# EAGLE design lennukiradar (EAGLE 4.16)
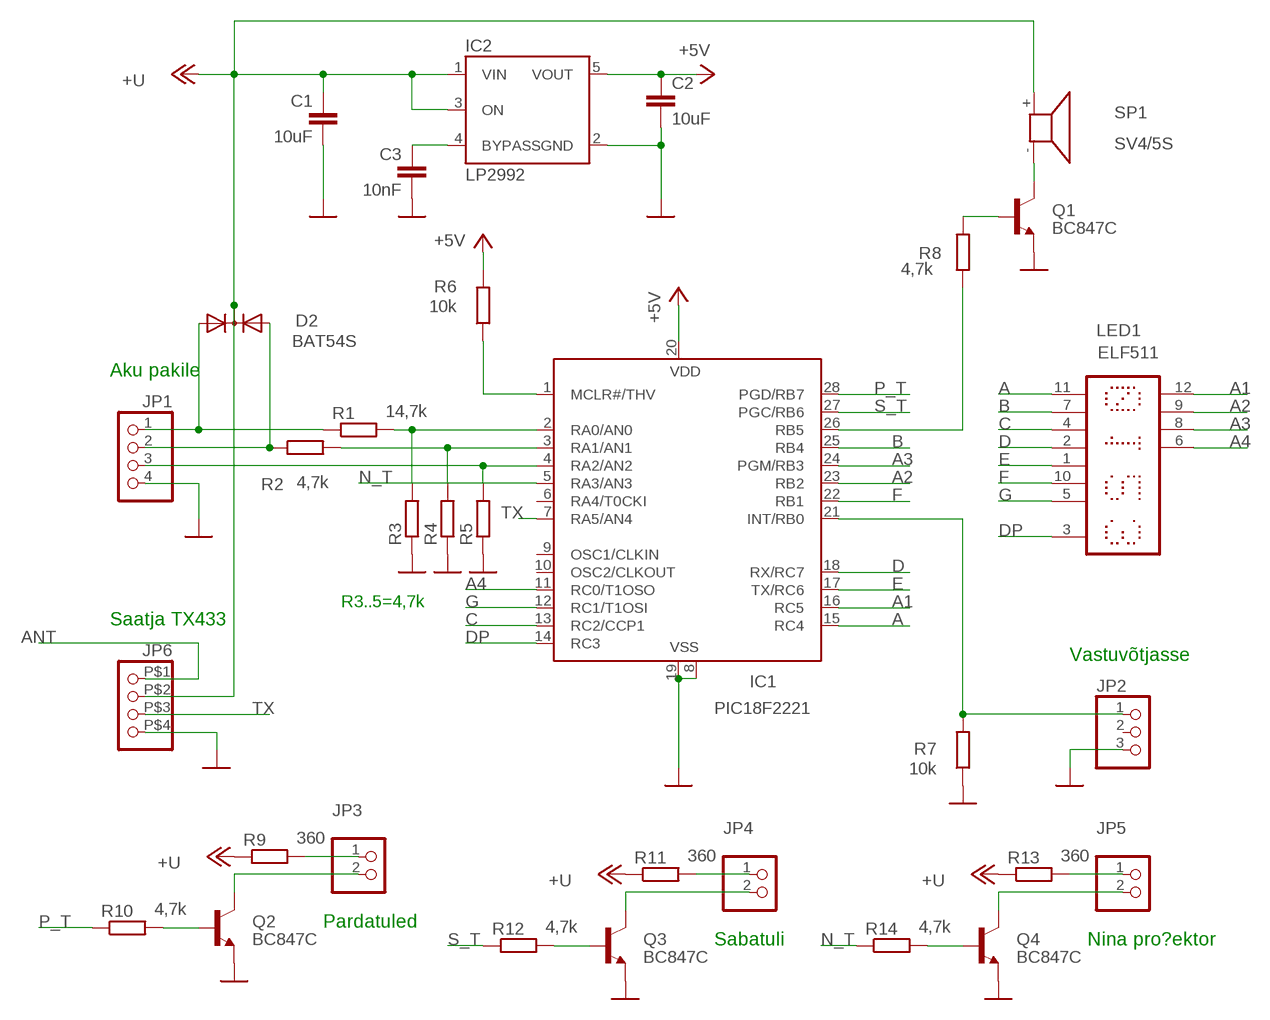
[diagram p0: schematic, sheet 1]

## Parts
C1  10uF  C-EUC0603K  [C0603K]
C2  10uF  C-EUC0603K  [C0603K]
C3  10nF  C-EUC0603K  [C0603K]
D2  BAT54S  BAS70-05  [SOT23]
IC1  PIC18F2221  PIC16F870SS  [SSOP28]
IC2  LP2992  LP2982M5  [SOT23-5]
JP1  PINHD-1X4  [1X04]
JP2  PINHD-1X3  [1X03]
JP3  PINHD-1X2  [1X02]
JP4  PINHD-1X2  [1X02]
JP5  PINHD-1X2  [1X02]
JP6  PINHD-1X4SMD  [1X04SMD]
LED1  ELF511  [ELF511]
Q1  BC847C  BC847CSMD  [SOT23]
Q2  BC847C  BC847CSMD  [SOT23]
Q3  BC847C  BC847CSMD  [SOT23]
Q4  BC847C  BC847CSMD  [SOT23]
R1  14,7k  R-EU_R0603  [R0603]
R2  4,7k  R-EU_R0603  [R0603]
R3  R-EU_R0603  [R0603]
R4  R-EU_R0603  [R0603]
R5  R-EU_R0603  [R0603]
R6  10k  R-EU_R0603  [R0603]
R7  10k  R-EU_R0603  [R0603]
R8  4,7k  R-EU_R0603  [R0603]
R9  360  R-EU_R0603  [R0603]
R10  4,7k  R-EU_R0603  [R0603]
R11  360  R-EU_R0603  [R0603]
R12  4,7k  R-EU_R0603  [R0603]
R13  360  R-EU_R0603  [R0603]
R14  4,7k  R-EU_R0603  [R0603]
SP1  SV4/5S  KSS1201  [KSS1201]

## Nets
+5V: C2.1 IC1.20(VDD) IC2.5(VOUT) R6.2
+12V: C1.1 D2.3(C) IC2.1(VIN) IC2.3(ON) JP6.P$2 R9.1 R11.1 R13.1 SP1.+ ; supply symbol labelled +U
A: IC1.15(RC4) LED1.11(A)
A1: IC1.16(RC5) LED1.12(COL1)
A2: IC1.23(RB2) LED1.9(COL2)
A3: IC1.24(PGM/RB3) LED1.8(COL3)
A4: IC1.11(RC0/T1OSO) LED1.6(COL4)
ANT: JP6.P$1
B: IC1.25(RB4) LED1.7(B)
C: IC1.13(RC2/CCP1) LED1.4(C)
D: IC1.18(RX/RC7) LED1.2(D)
DP: IC1.14(RC3) LED1.3(DP)
E: IC1.17(TX/RC6) LED1.1(E)
F: IC1.22(RB1) LED1.10(F)
G: IC1.12(RC1/T1OSI) LED1.5(G)
GND: C1.2 C2.2 C3.2 IC1.8(VSS) IC1.19(VSS) IC2.2(GND) JP1.4 JP2.3 JP6.P$4 Q1.2(E) Q2.2(E) Q3.2(E) Q4.2(E) R3.1 R4.1 R5.1 R7.1
N$1: JP3.2 Q2.3(C)
N$2: IC1.21(INT/RB0) JP2.1 R7.2
N$3: Q2.1(B) R10.2
N$4: D2.1(A1) JP1.2 R2.1
N$5: IC1.4(RA2/AN2) JP1.3 R5.2
N$6: C3.1 IC2.4(BYPASS)
N$7: Q1.1(B) R8.1
N$8: JP3.1 R9.2
N$9: Q1.3(C) SP1.-
N$10: D2.2(A2) JP1.1 R1.1
N$11: JP4.2 Q3.3(C)
N$12: JP4.1 R11.2
N$13: Q3.1(B) R12.2
N$14: IC1.2(RA0/AN0) R1.2 R3.2
N$15: IC1.3(RA1/AN1) R2.2 R4.2
N$17: JP5.2 Q4.3(C)
N$18: JP5.1 R13.2
N$19: Q4.1(B) R14.2
N$26: IC1.1(MCLR#/THV) R6.1
N$29: IC1.26(RB5) R8.2
N_T: IC1.5(RA3/AN3) R14.1
P_T: IC1.28(PGD/RB7) R10.1
S_T: IC1.27(PGC/RB6) R12.1
TX: IC1.7(RA5/AN4) JP6.P$3
Unconnected: IC1.6(RA4/T0CKI) IC1.9(OSC1/CLKIN) IC1.10(OSC2/CLKOUT) JP2.2

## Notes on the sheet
- Aku pakile
- R3..5=4,7k
- Saatja TX433
- Vastuvõtjasse
- Pardatuled
- Sabatuli | Nina pro?ektor

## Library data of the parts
C1-C3 = rcl:C-EU: CAPACITOR, European symbol
D2 = diode:BAS70-05: Silicon Schottky Diodes General-purpose diode for high-speed switching
IC1 = microchip-5:PIC16*870: MICROCONTROLLER flash type
IC2 = v-reg-3:LP2982: National Semiconductor Micropower Linear Regulator 50mA regulated output, Vin 16V max., ultra-low dropout of 120mV @ 50mA, 1µA standby current, low noise
JP1 JP6 = pinhead:PINHD-1X4: PIN HEADER
JP2 = pinhead:PINHD-1X3: PIN HEADER
JP3-JP5 = pinhead:PINHD-1X2: PIN HEADER
LED1 = led_disp:ELF511
Q1-Q4 = transistor-npn:BC847*: NPN Transistor
R1-R14 = rcl:R-EU_: RESISTOR, European symbol
SP1 = buzzer:KSS1201: SPEAKER

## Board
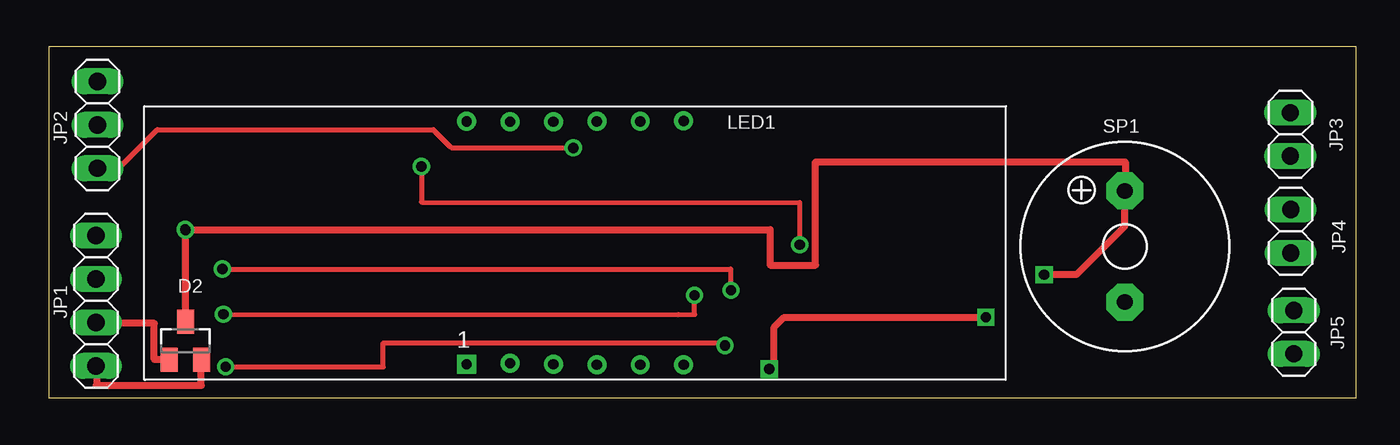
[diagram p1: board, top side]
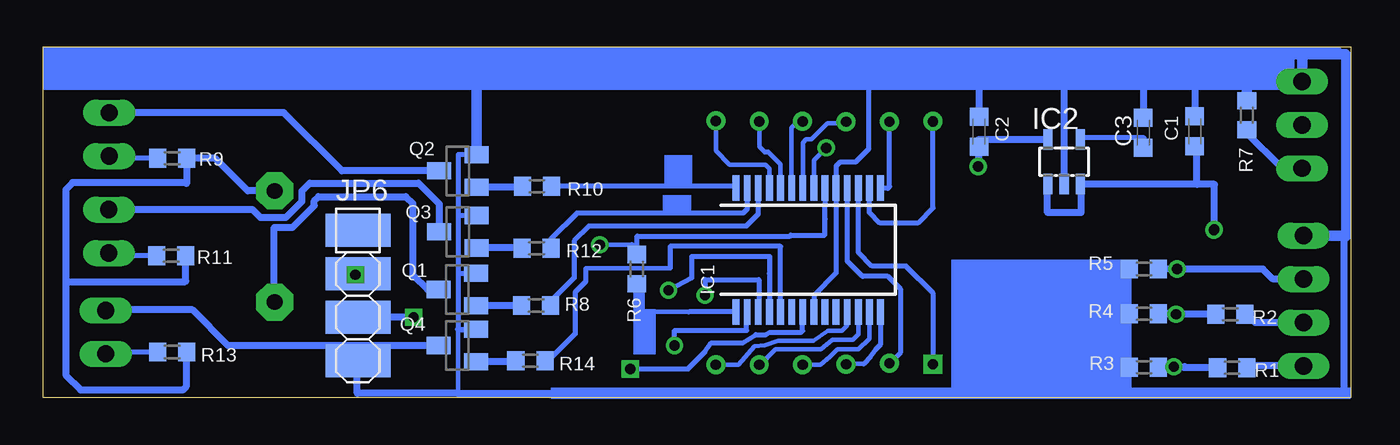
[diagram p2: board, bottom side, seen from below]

Size 76.48 x 20.52 mm. Coordinates in mm from the lower left corner, seen from the top.
Outline: 0,0 76.49,0 76.49,20.52 0,20.52 0,0
Copper layers (1*16): Top 0.035mm / dielectric 1.5mm / Bottom 0.035mm
Design rules "default": minimum track width 10mil, minimum drill 24mil, track to track 8mil, track to pad 8mil, pad to pad 8mil, via to via 8mil, smd to smd 8mil, copper to edge 40mil, drill to drill 8mil, minimum pad ring 10mil, minimum via ring 8mil, stop-mask expansion 4mil, vias tented up to drill 0mil, thermal gap 10mil

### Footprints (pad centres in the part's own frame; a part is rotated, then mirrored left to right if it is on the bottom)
C0603K = smd 1.05 x 1.08: 1 -0.875,0; 2 0.875,0
SOT23 = smd 1 x 1.4: 1 -0.95,-1.1; 2 0.95,-1.1; 3 0,1.1
SSOP28 = smd 0.4 x 1.5: 1 -4.225,-3.625; 2 -3.575,-3.625; 3 -2.925,-3.625; 4 -2.275,-3.625; 5 -1.625,-3.625; 6 -0.975,-3.625; 7 -0.325,-3.625; 8 0.325,-3.625; 9 0.975,-3.625; 10 1.625,-3.625; 11 2.275,-3.625; 12 2.925,-3.625; 13 3.575,-3.625; 14 4.225,-3.625; 15 4.225,3.625; 16 3.575,3.625; 17 2.925,3.625; 18 2.275,3.625; 19 1.625,3.625; 20 0.975,3.625; 21 0.325,3.625; 22 -0.325,3.625; 23 -0.975,3.625; 24 -1.625,3.625; 25 -2.275,3.625; 26 -2.925,3.625; 27 -3.575,3.625; 28 -4.225,3.625
SOT23-5 = smd 0.55 x 1.2: 1 -0.95,-1.3; 2 0,-1.3; 3 0.95,-1.3; 4 0.95,1.3; 5 -0.95,1.3
1X04 = drill 1.016 long: 1 -3.81,0; 2 -1.27,0; 3 1.27,0; 4 3.81,0
1X03 = drill 1.016 long: 1 -2.54,0; 2 0,0; 3 2.54,0
1X02 = drill 1.016 long: 1 -1.27,0; 2 1.27,0
1X04SMD = smd 1.93 x 3.81: P$1 -3.81,0; P$2 -1.27,0; P$3 1.27,0; P$4 3.81,0
ELF511 = drill 0.6 square: 1 -6.35,-7.087 | drill 0.6 round: 2 -3.81,-7.036; 3 -1.27,-7.087; 4 1.27,-7.112; 5 3.81,-7.112; 6 6.35,-7.112; 7 6.35,7.137; 8 3.81,7.112; 9 1.27,7.112; 10 -1.27,7.087; 11 -3.81,7.087; 12 -6.35,7.112
R0603 = smd 1 x 1.1: 1 -0.85,0; 2 0.85,0
KSS1201 = drill 0.914 pad 2.159 octagon: + 3.251,0; - -3.251,0

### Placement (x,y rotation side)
C1  9.11,15.58 90 bottom
C2  21.74,15.56 90 bottom
C3  12.14,15.51 90 bottom
D2  8,3.34 0 top
IC1  31.72,8.65 0 bottom
IC2  16.76,13.8 0 bottom
JP1  2.76,5.68 90 top
JP2  2.84,15.96 90 top
JP3  72.61,15.41 90 top
JP4  72.64,9.74 90 top
JP5  72.82,3.85 90 top
JP6  58.06,5.98 270 bottom
LED1  30.78,9.06 0 top
Q1  52.24,6.34 90 bottom
Q2  52.22,13.27 90 bottom
Q3  52.22,9.72 90 bottom
Q4  52.24,3.06 90 bottom
R1  6.93,1.77 180 bottom
R2  7.03,4.89 180 bottom
R3  12.09,1.79 0 bottom
R4  12.09,4.92 0 bottom
R5  12.09,7.53 0 bottom
R6  41.75,7.53 90 bottom
R7  6.07,16.52 270 bottom
R8  47.65,5.4 0 bottom
R9  68.93,14.01 180 bottom
R10  47.59,12.38 180 bottom
R11  68.98,8.32 180 bottom
R12  47.62,8.75 180 bottom
R13  68.93,2.68 180 bottom
R14  47.98,2.17 180 bottom
SP1  62.94,8.85 90 top

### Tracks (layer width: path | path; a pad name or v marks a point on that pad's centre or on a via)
+5V  (via drill 0.6)
  Top 0.305: v21.79,13.53 21.79,11.44 43.91,11.42 v43.91,8.95
  Bottom 0.305: 30.73,12.27 30.73,12.33 | 30.73,12.27 IC1.20 | 30.73,12.27 30.74,10.45 30.75,10.45 30.75,9.51 32.74,9.51 32.79,9.46 41.73,9.46 41.75,9.44 R6.2 41.75,8.62 41.73,8.65 42.06,8.98 v43.91,8.95 | C2.1 21.74,13.58 v21.79,13.53
  Bottom 0.406: C2.1 21.7,14.68 21.66,14.72 21.64,14.69 | 21.76,13.53 21.76,13.5 | 21.76,13.53 v21.79,13.53 | IC2.5 21.76,15.11 21.76,13.53
+12V  (via drill 0.6)
  Top 0.406: D2.3 v8,9.82 | v7.97,9.84 42.18,9.84 42.18,7.76 44.85,7.76 44.85,13.81 62.96,13.81 62.96,12.1 | 62.96,12.1 62.96,12.08 | 62.96,12.1 SP1.+ 62.99,12.1 62.91,12.03 62.91,10.02 60.09,7.2 v58.21,7.2
  Bottom 0.305: JP6.P$2 58.16,7.25 v58.21,7.2
  Bottom 0.406: R9.1 68.12,14.01 | R9.1 66.42,14.01 64.51,12.1 62.96,12.1 | R13.1 68.08,0.69 68.3,0.47 74.29,0.47 75.15,1.33 75.15,6.79 | 75.15,6.79 75.15,12.18 74.75,12.59 68.14,12.59 68.09,12.54 68.09,13.83 68.08,13.84 R9.1 | R11.1 68.13,6.83 68.17,6.79 75.15,6.79 | C1.1 9.22,14.62 9.19,14.72 9.22,14.69 8.99,14.69 8.99,12.48 | 15.77,12.48 15.77,12.51 | 8.99,12.48 15.77,12.48 | 15.77,12.48 15.77,12.46 | v8,9.82 7.97,9.82 v7.97,9.84 7.97,12.48 8.99,12.48 | 15.77,12.51 IC2.3 | 15.77,12.51 15.77,10.83 17.72,10.83 17.72,12.51 IC2.1 | SP1.+ 62.96,12.1 | 62.96,12.1 62.96,12.08
A
  Bottom 0.305: IC1.15 27.09,12.27 27.07,12.26 26.97,12.36 LED1.11
A1
  Bottom 0.305: IC1.16 28.14,10.84 27.53,10.22 25.32,10.22 24.43,11.11 24.43,16.07 24.4,16.09 24.43,16.12 LED1.12
A2
  Bottom 0.254: LED1.9 32.33,16.17 32.69,15.8 IC1.23
A3
  Bottom 0.254: IC1.24 33.34,13.65 34.06,14.36 | 34.26,14.36 34.59,14.69 LED1.8
  Bottom 0.305: 34.06,14.36 34.26,14.36
A4
  Bottom 0.254: LED1.6 35.81,1.94 34.87,3.01 34.26,3.09 33.5,3.34 31.42,3.34 30.58,3.92 29.76,3.92 29.46,4.23 29.46,4.99
  Bottom 0.305: 29.46,4.99 29.44,5.01 IC1.11
B
  Bottom 0.254: IC1.25 33.99,13.39 34.23,13.63 36.32,13.63 37.13,14.44 37.13,16.07
  Bottom 0.305: LED1.7 37.13,16.17 37.18,16.12 37.13,16.07
C
  Bottom 0.254: LED1.4 31.01,1.94 30.45,2.4 30.02,2.83 28.77,2.83 28.14,3.47 28.14,4.94
  Bottom 0.305: IC1.13 28.14,4.99 28.16,4.97 28.14,4.94
D
  Bottom 0.305: IC1.18 29.44,8 28.54,7.1 27.07,7.1 26.31,6.34 26.31,2.68 LED1.2
DP
  Bottom 0.305: LED1.3 28.47,1.99 28.09,2.4 27.76,2.83 27.48,3.14 27.48,4.99 27.49,5.01 IC1.14
E
  Bottom 0.305: IC1.17 28.79,8.52 27.99,7.71 26,7.71 24.4,6.11 24.4,2.07 24.51,1.97 | 24.51,1.97 24.56,1.92 | LED1.1 24.51,1.97
F
  Bottom 0.254: IC1.22 32.04,14.93 31.85,15.13 31.54,15.13 30.6,16.07 29.56,16.07
  Bottom 0.305: 29.48,16.14 29.46,16.17 | 29.48,16.14 LED1.10 | 29.56,16.07 29.48,16.14
G
  Bottom 0.254: LED1.5 34.62,1.94 34.54,1.92 | 34.16,2.32 33.65,2.83 30.98,2.83 30.3,3.39 29.1,3.39 28.77,3.72 28.77,4.81
  Bottom 0.305: 34.16,2.32 34.54,1.92 | IC1.12 28.79,4.89 28.75,4.84 28.77,4.81
GND
  Bottom 0.254: Q4.2 52.27,4.01 52.27,4.03 52.22,4.03 52.22,0.27
  Bottom 0.305: Q2.2 52.19,14.22 52.19,10.71 | 52.19,7.28 52.19,3.98 51.07,3.98 51.07,4.01 Q4.2 | 52.19,10.71 52.19,7.28 | 52.19,7.28 52.17,7.28 52.17,7.29 Q1.2 | Q3.2 52.19,10.67 52.19,10.71 | 28.19,20.1 28.19,20.08 28.21,20.05 | R5.1 12.94,4.93 R4.1 12.94,1.86 12.97,1.82 12.95,1.79 R3.1 12.94,0.36 12.97,0.32 11.48,0.32 | 28.14,20.1 28.14,20.03 28.19,19.98 28.19,14.54 28.95,13.78 29.87,13.78 30.09,13.55 IC1.19 30.09,7.3 31.39,6 IC1.8
  Bottom 0.406: 9.11,20.1 C1.2 | 21.81,20.1 21.81,20.03 21.74,19.95 C2.2 | 16.3,20.1 16.23,20.03 | 11.5,0.32 11.48,0.32 0.38,0.32 0.38,9.49 | 12.14,20.1 C3.2 | 16.76,20.13 16.76,20.1 IC2.2 | JP6.P$4 58.11,2.17 58.11,0.27 52.22,0.27 46.27,0.27 46.27,0.17
  Bottom 0.61: JP1.4 0.38,9.49 0.25,9.49 0.25,20.03 0.33,20.1 2.87,20.1 | 2.87,20.1 6.12,20.1 | 6.12,20.1 9.11,20.1 12.14,20.1 16.3,20.1 16.76,20.1 21.81,20.1 28.14,20.1 28.19,20.1 51.07,20.1 51.13,20.16 51.13,14.26 51.08,14.22 | 51.08,14.22 51.02,14.16 | 51.08,14.22 Q2.2 | 2.87,20.1 2.87,20.05 2.84,20.03 JP2.3 | 6.12,20.1 6.12,19.85 6.07,19.8 R7.1
N$1
  Bottom 0.305: JP3.2 72.61,16.83 72.46,16.68
  Bottom 0.406: Q2.3 59,13.27 62.4,16.68 72.46,16.68
N$2  (via drill 0.6)
  Top 0.305: v30.68,14.62 23.57,14.62 23.46,14.69 22.47,15.68 6.35,15.68 4.21,13.55 4.14,13.55 3.98,13.4 2.87,13.4 JP2.1
  Bottom 0.254: v30.68,14.62 31.39,13.91 31.39,12.38
  Bottom 0.305: IC1.21 31.39,12.34 31.42,12.36 31.39,12.38
  Bottom 0.406: R7.2 6.07,15.58 6.12,15.53 4.01,13.42 JP2.1
N$3
  Bottom 0.406: R10.2 48.48,12.38 48.54,12.32 Q2.1
N$4
  Top 0.406: 2.89,4.41 2.89,4.36 | 2.89,4.41 JP1.2 2.94,4.41 2.94,4.36 6.17,4.36 6.17,2.24 D2.1 | 2.89,4.41 2.89,4.44
  Bottom 0.406: R2.1 6.18,4.93 6.14,4.97 5.58,4.41 JP1.2
N$5  (via drill 0.6)
  Top 0.305: v39.9,6.29 39.87,6.29 39.87,7.53 v10.16,7.53 10.03,7.53
  Bottom 0.305: IC1.4 33.99,7.27 33.98,8.27 38.53,8.27 38.53,7.02 v39.9,6.29 | 9.83,7.53 9.83,7.56 v10.16,7.53
  Bottom 0.406: JP1.3 4.54,6.95 5.13,7.53 9.83,7.53 9.95,7.53 9.99,7.57 | 9.99,7.57 10,7.58 | 9.99,7.57 R5.2
N$6
  Bottom 0.305: IC2.4 15.79,15.11 15.79,15.2 12.09,15.2 12.09,14.63 C3.1
N$7
  Bottom 0.406: R8.1 48.36,5.4 48.37,5.39 Q1.1
N$8
  Bottom 0.305: JP3.1 72.61,14.26 72.36,14.01 R9.2
N$9
  Bottom 0.305: SP1.- 62.96,5.63
  Bottom 0.406: 62.96,5.63 62.96,9.97 61.9,9.97 60.63,11.24 60.63,11.52 60.37,11.77 55.27,11.77 54.86,11.37 54.86,7.2 54,6.34 53.44,6.34 53.41,6.36 53.39,6.34 Q1.3
N$10
  Top 0.406: 2.74,1.87 2.76,1.89 JP1.1 2.79,1.87 2.79,0.72 | D2.2 8.91,2.24 8.91,0.72 2.79,0.72 | 2.79,0.72 2.76,0.72
  Bottom 0.406: R1.1 5.89,1.77 5.79,1.87 JP1.1
N$11
  Bottom 0.305: JP4.2 72.66,11.01 72.69,11.04
  Bottom 0.406: 72.66,11.01 64.23,11.01 63.77,10.55 62.28,10.55 61.34,11.49 61.34,12.1 60.88,12.56 54.53,12.56 53.31,11.34 53.31,10.05 53.34,10.02 53.32,10 Q3.3
N$12
  Bottom 0.305: JP4.1 72.64,8.5 72.46,8.32 R11.2
N$13
  Bottom 0.406: R12.2 48.51,8.75 48.56,8.7 48.63,8.77 Q3.1
N$14  (via drill 0.6)
  Top 0.305: v10.33,1.82 19.55,1.82 19.55,3.21 39.52,3.21 39.59,3.06 v39.54,3.06
  Bottom 0.305: R3.2 10.69,1.79 v10.33,1.82 | 35.35,4.69 35.28,4.76 35.29,4.78 IC1.2 35.29,4.9 35.3,4.92 35.33,3.95 39.54,3.95 v39.54,3.06
  Bottom 0.406: R3.2 9.77,1.79 9.72,1.84 9.65,1.77 R1.2
N$15  (via drill 0.6)
  Top 0.305: v37.77,6.01 37.77,4.89 36.8,4.86 v10.21,4.89
  Bottom 0.305: R4.2 9.83,4.92 v10.21,4.89 | 34.62,4.81 34.64,4.84 IC1.3 | 34.62,4.81 34.64,4.79 | 34.62,4.81 34.62,6.92 37.74,6.92 v37.77,6.01
  Bottom 0.406: 9.99,4.93 10,4.94 | 9.99,4.93 R4.2 | R2.2 9.95,4.89 9.99,4.93
N$17
  Bottom 0.305: 72.74,5.14 72.77,5.12 JP5.2
  Bottom 0.406: Q4.3 65.65,3.06 67.74,5.14 72.74,5.14
N$18
  Bottom 0.305: R13.2 72.72,2.68 JP5.1
N$19
  Bottom 0.406: R14.2 48.84,2.17 48.9,2.11 Q4.1
N$26
  Bottom 0.305: IC1.1 38.71,5.02 41.75,5.02 R6.1
N$29
  Bottom 0.305: R8.2 46.8,5.64 45.41,7.02 45.41,9.18 44.55,10.05 35.35,10.05 34.64,10.76 34.64,12.21 IC1.26
N_T
  Bottom 0.305: R14.1 46.93,2.17 45.36,3.75 45.36,6.19 44.75,6.79 44.75,7.53 44.72,7.56 39.8,7.58 39.8,8.85 33.35,8.85 33.35,5.09 33.34,5.09 IC1.5
P_T
  Bottom 0.305: IC1.28 36.01,12.27 36.11,12.38 R10.1
S_T
  Bottom 0.305: R12.1 46.77,9.3 45.26,10.81 35.53,10.81 35.3,11.04 35.3,12.1 35.29,12.11 IC1.27
TX  (via drill 0.6)
  Top 0.406: v54.81,4.71 43,4.71 42.41,4.13 42.41,1.97 v42.13,1.69
  Bottom 0.305: 41.7,1.69 38.76,1.69 37.79,2.65 37.41,3.21 35.56,3.21 34.79,3.7 34.18,3.7 33.98,3.82 32.15,3.82 32.05,3.92 32.05,4.84 32.02,4.86 32.04,4.88 IC1.7
  Bottom 0.406: v54.81,4.71 JP6.P$3 | v42.13,1.69 41.7,1.69
(copper drawn outside any net)
  shapes: Bottom area x9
